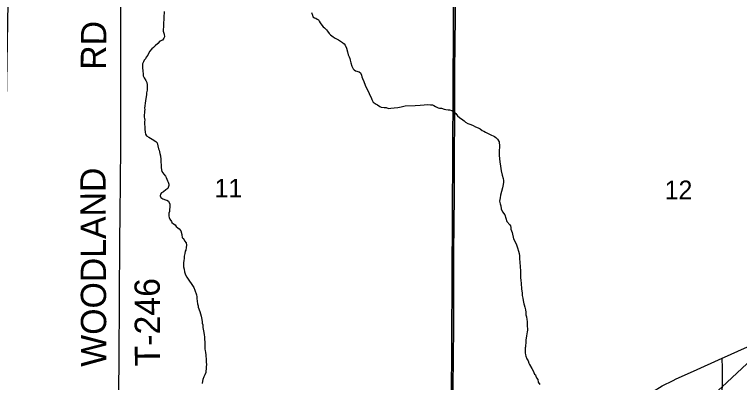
# Model space of a CAD drawing. Extents: x 0 to 34, y 0 to 22.
# Drawn here: x 6.537 to 8.166, y 18.505 to 19.332 of the extents above; entities that cross this region are included whole.
import ezdxf

# ---------------------------------------------------------------- set-up
doc = ezdxf.new("R2010")
doc.units = 0
for name, color, linetype in [('GM_X_City_Street', 7, 'Continuous'), ('GM_X_Minor_River', 7, 'Continuous'), ('GM_X_Rail_Line', 7, 'Continuous'), ('GM_X_Section', 7, 'Continuous'), ('GM_X_Section_Text', 7, 'Continuous'), ('GM_X_State_Route', 7, 'Continuous'), ('GM_X_Township_Road', 7, 'Continuous'), ('GM_X_Township_Road_Text', 7, 'Continuous')]:
    doc.layers.add(name, color=color, linetype=linetype)

msp = doc.modelspace()

# ---------------------------------------------------------------- linework, layer by layer
at = {"layer": 'GM_X_City_Street'}
msp.add_lwpolyline([(8.1145, 17.9288), (8.1172, 17.9364), (8.1186, 17.9462), (8.1196, 17.9837), (8.1212, 18.0823), (8.1229, 18.2067), (8.1249, 18.3272), (8.1268, 18.4478), (8.1277, 18.5373), (8.1268, 18.5594)], dxfattribs=at)
at = {"layer": 'GM_X_Minor_River'}
for points in [[(6.8735, 19.3388), (6.8728, 19.3259), (6.8725, 19.3198), (6.8717, 19.3153), (6.8714, 19.305), (6.8707, 19.2982), (6.8707, 19.2951), (6.873, 19.2883), (6.8738, 19.2822), (6.8727, 19.2788), (6.8693, 19.275), (6.8636, 19.2723), (6.8591, 19.2673), (6.8534, 19.2616), (6.8493, 19.2582), (6.8455, 19.2551), (6.8406, 19.2494), (6.8364, 19.241), (6.833, 19.2361), (6.8312, 19.233), (6.8285, 19.23), (6.827, 19.2258), (6.8244, 19.2212), (6.8244, 19.2113), (6.8252, 19.2072), (6.8256, 19.2037), (6.826, 19.2007), (6.8264, 19.1942), (6.828, 19.1901), (6.8322, 19.184), (6.8341, 19.1795), (6.8353, 19.1742), (6.8353, 19.1685), (6.8349, 19.162), (6.8342, 19.1593), (6.8338, 19.1563), (6.8335, 19.1514), (6.8324, 19.1438), (6.8309, 19.1327), (6.8298, 19.127), (6.8294, 19.1217), (6.8295, 19.1191), (6.8291, 19.1153), (6.8291, 19.1122), (6.828, 19.1058), (6.828, 19.1016), (6.8292, 19.0982), (6.8296, 19.0947), (6.8292, 19.0921), (6.8292, 19.0841), (6.8296, 19.0811), (6.8297, 19.0742), (6.8305, 19.0678), (6.8316, 19.0636), (6.8335, 19.0594), (6.8385, 19.0568), (6.8461, 19.0523), (6.8545, 19.047), (6.8572, 19.0436), (6.8591, 19.0372), (6.8606, 19.0303), (6.8618, 19.0277), (6.8633, 19.0201), (6.8649, 19.0144), (6.8657, 19.0064), (6.8662, 18.9882), (6.8673, 18.9829), (6.8681, 18.9791), (6.87, 18.9764), (6.8723, 18.973)], [(7.2045, 19.337), (7.2069, 19.3305), (7.2076, 19.3271), (7.2107, 19.3252), (7.2137, 19.3241), (7.2171, 19.3222), (7.2198, 19.3203), (7.2213, 19.3177), (7.224, 19.3139), (7.2256, 19.3112), (7.2305, 19.3048), (7.2336, 19.3026), (7.2381, 19.2976), (7.2404, 19.2946), (7.2443, 19.2897), (7.2473, 19.2863), (7.25, 19.284), (7.253, 19.2818), (7.2576, 19.2791), (7.2618, 19.2769), (7.2648, 19.2754), (7.274, 19.2693), (7.2774, 19.2667), (7.2801, 19.2633), (7.2828, 19.2568), (7.2851, 19.2485), (7.287, 19.242), (7.2893, 19.2371), (7.2905, 19.2333), (7.2912, 19.2295), (7.2924, 19.2234), (7.2947, 19.2162), (7.2978, 19.2102), (7.3005, 19.2079), (7.3035, 19.2056), (7.3115, 19.2038), (7.3145, 19.2015), (7.3168, 19.1958), (7.3176, 19.1924), (7.3188, 19.1886), (7.3219, 19.1818), (7.3249, 19.1735), (7.3288, 19.1651), (7.3326, 19.1587), (7.3357, 19.1507), (7.338, 19.1454), (7.3395, 19.1416), (7.341, 19.1386), (7.3426, 19.1352), (7.3498, 19.1307), (7.3529, 19.1292), (7.3582, 19.1258), (7.3612, 19.1239), (7.3677, 19.1235), (7.3723, 19.1232), (7.3772, 19.1213), (7.3825, 19.1221), (7.3901, 19.1225), (7.3981, 19.1229)], [(7.3981, 19.1229), (7.4056, 19.1249), (7.4151, 19.1268), (7.4371, 19.1277), (7.4481, 19.1285), (7.4573, 19.1289), (7.4656, 19.1297), (7.4717, 19.1293), (7.4759, 19.129), (7.4789, 19.1279), (7.4831, 19.1256), (7.4888, 19.1226), (7.4922, 19.1218), (7.4964, 19.1215), (7.5025, 19.1196), (7.5063, 19.1185), (7.5116, 19.1181), (7.5146, 19.1178), (7.5196, 19.1163), (7.5241, 19.1136), (7.5283, 19.1095), (7.5325, 19.1046), (7.5367, 19.1008), (7.5443, 19.0955), (7.547, 19.0932), (7.5504, 19.0906), (7.5558, 19.0876), (7.5622, 19.0853), (7.5672, 19.0831), (7.5729, 19.0801), (7.5786, 19.0778), (7.5835, 19.0752), (7.5881, 19.0718), (7.5915, 19.0699), (7.5953, 19.068), (7.5995, 19.0658), (7.6045, 19.0631), (7.6087, 19.0613), (7.6121, 19.0594), (7.6151, 19.0579), (7.6186, 19.0556), (7.6224, 19.0522), (7.6262, 19.0458), (7.6266, 19.0366), (7.6256, 19.0241), (7.626, 19.015), (7.6276, 19.0013), (7.6288, 18.9911), (7.6307, 18.9808), (7.6326, 18.9713), (7.6346, 18.9638), (7.6354, 18.9592), (7.6358, 18.9554), (7.635, 18.9501), (7.6332, 18.9429), (7.6291, 18.9261), (7.6283, 18.9204), (7.6276, 18.9162), (7.6269, 18.9124), (7.6273, 18.9094), (7.628, 18.9068), (7.6296, 18.9022), (7.6304, 18.8954), (7.6338, 18.8889), (7.6388, 18.8817), (7.6434, 18.8673), (7.6499, 18.8598), (7.6514, 18.8571), (7.6518, 18.8533), (7.6522, 18.8499), (7.6553, 18.8419), (7.6584, 18.8279), (7.6642, 18.8169), (7.6672, 18.8078), (7.6692, 18.8002), (7.6707, 18.7949), (7.6715, 18.79), (7.6719, 18.7831), (7.6723, 18.7752), (7.6731, 18.7653), (7.6736, 18.7562), (7.6736, 18.7482), (7.674, 18.7402), (7.6744, 18.7353), (7.6752, 18.7273), (7.6764, 18.7159), (7.6772, 18.7102), (7.6776, 18.7068), (7.678, 18.7008), (7.6788, 18.6943), (7.6796, 18.6894), (7.6808, 18.6856), (7.6815, 18.6822), (7.6819, 18.6795), (7.6835, 18.6742), (7.685, 18.6685), (7.6858, 18.6628), (7.6862, 18.6571), (7.687, 18.6526), (7.6878, 18.6469), (7.6886, 18.6423)], [(6.8723, 18.973), (6.8765, 18.9689), (6.878, 18.9658), (6.8811, 18.9586), (6.8826, 18.9556), (6.8838, 18.9507), (6.8834, 18.948), (6.8812, 18.9415), (6.877, 18.9381), (6.8721, 18.9339), (6.8676, 18.9316), (6.8649, 18.9285), (6.8642, 18.9244), (6.8657, 18.921), (6.8703, 18.9179), (6.876, 18.9157), (6.8794, 18.9146), (6.8832, 18.9123), (6.8859, 18.9062), (6.8863, 18.9028), (6.8863, 18.8994), (6.8856, 18.8941), (6.8849, 18.8891), (6.8841, 18.8857), (6.8838, 18.8831), (6.8838, 18.8789), (6.8842, 18.8758), (6.8857, 18.8721), (6.8895, 18.8671), (6.8907, 18.8645), (6.8941, 18.8618), (6.8979, 18.8596), (6.9006, 18.8558), (6.904, 18.8528), (6.9067, 18.8501), (6.9105, 18.8456), (6.9128, 18.8376), (6.9136, 18.83), (6.9167, 18.8285), (6.9186, 18.8236), (6.9228, 18.8191), (6.9232, 18.8137), (6.9225, 18.8088), (6.9217, 18.8027), (6.9206, 18.8001), (6.9199, 18.7951), (6.9184, 18.7887), (6.918, 18.7845), (6.9173, 18.7788), (6.9166, 18.775), (6.9166, 18.7693), (6.917, 18.7647), (6.9182, 18.7598), (6.9193, 18.7537), (6.9213, 18.7473), (6.9239, 18.7416), (6.927, 18.737), (6.9301, 18.7329), (6.9339, 18.7272), (6.9373, 18.7227), (6.94, 18.7185), (6.9423, 18.7124), (6.9458, 18.7022), (6.9466, 18.6976), (6.947, 18.6935), (6.9477, 18.6881), (6.9485, 18.6817), (6.9493, 18.6771), (6.9497, 18.6745), (6.9536, 18.6646), (6.9566, 18.654), (6.9578, 18.6464), (6.9586, 18.6415), (6.959, 18.6381), (6.9598, 18.6343), (6.9602, 18.6289), (6.9617, 18.621), (6.9629, 18.613), (6.9637, 18.6069), (6.9637, 18.6043), (6.9641, 18.6012), (6.9645, 18.5971), (6.9646, 18.5906), (6.965, 18.5834), (6.965, 18.5796), (6.9654, 18.5769), (6.9658, 18.5724), (6.9666, 18.5674), (6.9666, 18.564), (6.9674, 18.558), (6.9678, 18.5542), (6.9678, 18.5507), (6.9682, 18.5451), (6.9678, 18.5405), (6.9679, 18.5359), (6.9671, 18.5306), (6.9668, 18.5272), (6.9649, 18.5219), (6.9626, 18.5177), (6.9604, 18.512), (6.9593, 18.5082)], [(7.6886, 18.6423), (7.689, 18.6378), (7.689, 18.6309), (7.6894, 18.6264), (7.6894, 18.6229), (7.6891, 18.6188), (7.6883, 18.6146), (7.6876, 18.61), (7.6868, 18.6047), (7.6861, 18.6009), (7.6861, 18.5979), (7.6858, 18.5933), (7.6854, 18.5891), (7.685, 18.5853), (7.6847, 18.5827), (7.6847, 18.5716), (7.6851, 18.5671), (7.6855, 18.5644), (7.6882, 18.5584), (7.6909, 18.5534), (7.6924, 18.5485), (7.694, 18.5455), (7.699, 18.5364), (7.702, 18.5315), (7.7051, 18.5239), (7.7078, 18.522), (7.7085, 18.519), (7.7101, 18.5156), (7.7127, 18.5114), (7.7139, 18.5057), (7.717, 18.5004)], [(6.9593, 18.5082), (6.9589, 18.5028)]]:
    msp.add_lwpolyline(points, dxfattribs=at)
at = {"layer": 'GM_X_Rail_Line'}
msp.add_lwpolyline([(7.6757, 18.0934), (7.7402, 18.1481), (7.8743, 18.2711), (8.1262, 18.4945), (8.4641, 18.8097), (8.6445, 18.9615), (8.7545, 19.0553), (8.9, 19.1876)], dxfattribs=at)
at = {"layer": 'GM_X_Section'}
for points in [[(6.5246, 19.4487), (7.5241, 19.4466), (7.5189, 18.4589), (6.5078, 18.4687)], [(7.5241, 19.4466), (8.547, 19.4493), (8.532, 18.4506), (7.5189, 18.4589)]]:
    msp.add_lwpolyline(points, close=True, dxfattribs=at)
at = {"layer": 'GM_X_State_Route'}
for points in [[(7.5243, 18.7703), (7.5244, 18.7991), (7.525, 18.8586), (7.5253, 18.9271), (7.5258, 19.0141), (7.5265, 19.1008), (7.5267, 19.2058), (7.528, 19.327), (7.5295, 19.4511)], [(7.5241, 18.6997), (7.5241, 18.7464), (7.5243, 18.7703)], [(8.1322, 18.5619), (8.2135, 18.5984), (8.3377, 18.6539), (8.4774, 18.7168), (8.5339, 18.7422), (8.539, 18.7445)], [(7.5227, 18.4496), (7.5229, 18.4897), (7.5234, 18.5651), (7.5238, 18.6247), (7.5241, 18.6895), (7.5241, 18.6997)], [(8.0239, 18.5131), (8.0623, 18.5307), (8.1268, 18.5594), (8.1322, 18.5619)], [(7.6994, 18.0838), (7.7092, 18.0975), (7.7331, 18.1356), (7.7513, 18.165), (7.7697, 18.1938), (7.7941, 18.2334), (7.8142, 18.2647), (7.8523, 18.3248), (7.8844, 18.3749), (7.9062, 18.4091), (7.9269, 18.4394), (7.9375, 18.454), (7.9522, 18.4689), (7.9708, 18.4839), (7.9923, 18.4976), (8.0167, 18.5098), (8.0239, 18.5131)]]:
    msp.add_lwpolyline(points, dxfattribs=at)
at = {"layer": 'GM_X_Township_Road'}
for points in [[(6.7743, 18.8809), (6.7759, 19.0338), (6.7759, 19.3078), (6.7761, 19.4529)], [(6.7725, 18.5555), (6.7725, 18.5585), (6.7737, 18.8247), (6.7743, 18.8809)], [(6.7709, 18.4179), (6.771, 18.421), (6.7725, 18.5555)]]:
    msp.add_lwpolyline(points, dxfattribs=at)

# ---------------------------------------------------------------- texts
at = {"layer": 'GM_X_Section_Text'}
for s, p in [('11', (6.9865, 18.921)), ('12', (7.9978, 18.9171))]:
    msp.add_text(s, height=0.04186, rotation=0, dxfattribs=at).set_placement(p)
at = {"layer": 'GM_X_Township_Road_Text'}
for s, rotation, p in [('RD', 89.5045, (6.7425, 19.2078)), ('WOODLAND', 90.2333, (6.7434, 18.5407)), ('T-246', 90.2818, (6.8643, 18.5414))]:
    msp.add_text(s, height=0.05682, rotation=rotation, dxfattribs=at).set_placement(p)

doc.saveas('drawing.dxf')
